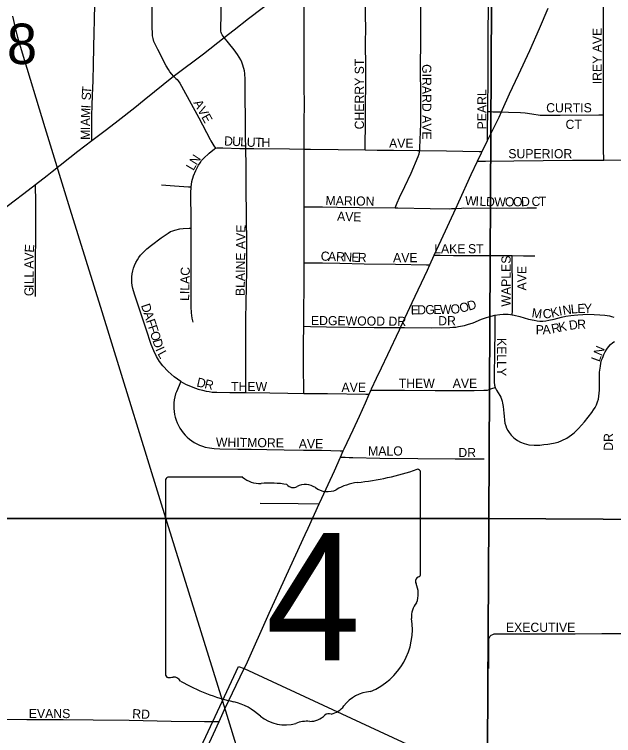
# Model space of a CAD drawing. Extents: x -97 to 34, y -21 to 22.
# Drawn here: x 5.1 to 5.72, y 18.248 to 18.994 of the extents above; entities that cross this region are included whole.
import ezdxf

# ---------------------------------------------------------------- set-up
doc = ezdxf.new("R2010")
doc.units = 0
for name, color, linetype in [('GM_X_City_Street', 7, 'Continuous'), ('GM_X_City_Street_Text', 7, 'Continuous'), ('GM_X_Corporation', 7, 'Continuous'), ('GM_X_Rail_Line', 7, 'Continuous'), ('GM_X_Section', 7, 'Continuous'), ('GM_X_Section_Text', 7, 'Continuous'), ('GM_X_State_Location', 7, 'Continuous'), ('GM_X_State_Route', 7, 'Continuous'), ('GM_X_State_Shield', 7, 'Continuous')]:
    doc.layers.add(name, color=color, linetype=linetype)

msp = doc.modelspace()

# ---------------------------------------------------------------- linework, layer by layer
at = {"layer": 'GM_X_City_Street'}
for points in [[(5.58975, 18.8933), (5.59013, 18.93041), (5.59013, 18.96145), (5.59029, 18.9801), (5.59084, 19.01111), (5.59091, 19.04212), (5.59113, 19.07316), (5.59112, 19.11343), (5.59118, 19.14442), (5.59129, 19.17858), (5.59144, 19.1837)], [(5.3172, 18.96983), (5.31523, 18.97259), (5.31429, 18.97411), (5.314, 18.975), (5.31386, 18.97623), (5.31375, 18.97746), (5.31377, 18.9795), (5.31391, 18.99294), (5.31363, 19.01437), (5.31364, 19.03294), (5.31356, 19.06369), (5.31328, 19.11002), (5.31303, 19.12908)], [(5.51942, 18.85279), (5.51963, 18.85569), (5.52056, 18.88044), (5.52045, 18.90837), (5.52015, 18.93892), (5.52047, 18.96678), (5.52058, 18.99042), (5.5204, 19.01152), (5.5206, 19.04541), (5.5203, 19.07025), (5.52029, 19.08893), (5.52037, 19.09845), (5.52047, 19.10759), (5.52043, 19.11067), (5.5202, 19.11689), (5.52, 19.11999), (5.51957, 19.12641)], [(5.46308, 18.85354), (5.46314, 18.85819), (5.4632, 18.88041), (5.46325, 18.89909), (5.46352, 18.92224), (5.46356, 18.93777), (5.46342, 18.96572), (5.46349, 18.97815), (5.46346, 18.99369), (5.46347, 19.00917), (5.46363, 19.0233), (5.46365, 19.04047), (5.46368, 19.06195), (5.46385, 19.07747), (5.46381, 19.0824)], [(5.3998, 18.85438), (5.40003, 18.88233), (5.40021, 18.90094), (5.39994, 18.91951), (5.40003, 18.94435), (5.39999, 18.96606), (5.39999, 18.97848), (5.40006, 19.00019), (5.40003, 19.00945), (5.39983, 19.01409), (5.3997, 19.01685), (5.39926, 19.01996), (5.39796, 19.0233), (5.39656, 19.02543), (5.39363, 19.02959)], [(5.18049, 18.86326), (5.18049, 18.87169), (5.18048, 18.88866), (5.18084, 18.89981), (5.18117, 18.90987), (5.1816, 18.92531), (5.18205, 18.94184), (5.18254, 18.9594), (5.18286, 18.97508), (5.18311, 18.98738), (5.18342, 19.00488), (5.18346, 19.01528)], [(5.26493, 18.92974), (5.26308, 18.93184), (5.26112, 18.93432), (5.25956, 18.93659), (5.25716, 18.94066), (5.24848, 18.95728), (5.24459, 18.96576), (5.24361, 18.96869), (5.24334, 18.97006), (5.24302, 18.97172), (5.24293, 18.97367), (5.2426, 18.98101), (5.24259, 18.99342), (5.24246, 19.01207), (5.2425, 19.01428)], [(5.70943, 18.88967), (5.70942, 18.91883), (5.70936, 18.98514), (5.70929, 19.00356), (5.70936, 19.00915)], [(5.33947, 18.8551), (5.33916, 18.86757), (5.33882, 18.92639), (5.33853, 18.9325), (5.33807, 18.93547), (5.33655, 18.94134), (5.3355, 18.94417), (5.33424, 18.9469), (5.3311, 18.95212), (5.32751, 18.9571), (5.32171, 18.96425), (5.3172, 18.96983)], [(5.26493, 18.92974), (5.26724, 18.92749), (5.26845, 18.92623), (5.26958, 18.92488), (5.27123, 18.92247), (5.27306, 18.91952), (5.291, 18.88661), (5.30255, 18.86447), (5.30344, 18.86284), (5.30663, 18.85763), (5.30832, 18.85538)], [(5.58948, 18.86336), (5.58956, 18.87486), (5.58975, 18.8933)], [(5.58975, 18.8933), (5.59203, 18.89317), (5.59504, 18.893), (5.59829, 18.89291), (5.60042, 18.89285), (5.60383, 18.89282)], [(5.60383, 18.89282), (5.61104, 18.89274), (5.62353, 18.89232), (5.62847, 18.89189), (5.63072, 18.89162), (5.63749, 18.89044), (5.64169, 18.88977), (5.64401, 18.88962), (5.66472, 18.88955), (5.70475, 18.88966), (5.70943, 18.88967)], [(5.7096, 18.84299), (5.7096, 18.8438), (5.70956, 18.85315), (5.70943, 18.88952), (5.70943, 18.88967)], [(5.28311, 18.81528), (5.28329, 18.81784), (5.28381, 18.8208), (5.28547, 18.82666), (5.28773, 18.83232), (5.29063, 18.83766), (5.29232, 18.84018), (5.29386, 18.84242), (5.29588, 18.84469), (5.30165, 18.8501), (5.30725, 18.85469), (5.30832, 18.85538)], [(5.30832, 18.85538), (5.30956, 18.85556), (5.31108, 18.85566), (5.31566, 18.8558), (5.33347, 18.85517), (5.33947, 18.8551)], [(5.33944, 18.60253), (5.33963, 18.61703), (5.33973, 18.6479), (5.33957, 18.67884), (5.34049, 18.72839), (5.34066, 18.75939), (5.34043, 18.7811), (5.33982, 18.81816), (5.33985, 18.83661), (5.33947, 18.8551)], [(5.33947, 18.8551), (5.34787, 18.855), (5.38474, 18.85459), (5.3998, 18.85438)], [(5.39994, 18.79478), (5.39986, 18.805), (5.39975, 18.84826), (5.3998, 18.85438)], [(5.3998, 18.85438), (5.40657, 18.85425), (5.4351, 18.85387), (5.46308, 18.85354)], [(5.46308, 18.85354), (5.47522, 18.85344), (5.49237, 18.85317), (5.51699, 18.85282), (5.51942, 18.85279)], [(5.49388, 18.79349), (5.49614, 18.79865), (5.49863, 18.80433), (5.50391, 18.81558), (5.51043, 18.82961), (5.51779, 18.84661), (5.5187, 18.84958), (5.51942, 18.85279)], [(5.51942, 18.85279), (5.54714, 18.85244), (5.58075, 18.85185), (5.58388, 18.8518)], [(5.57923, 18.84191), (5.58724, 18.84198), (5.61683, 18.84222), (5.67739, 18.84278), (5.7096, 18.84299)], [(5.7096, 18.84299), (5.73222, 18.84315), (5.76238, 18.84357), (5.77917, 18.84381), (5.78232, 18.84388)], [(5.12218, 18.70202), (5.12207, 18.70508), (5.12196, 18.71431), (5.12223, 18.72664), (5.12202, 18.74512), (5.12228, 18.75744), (5.12228, 18.76669), (5.12231, 18.80677), (5.12225, 18.80984), (5.12212, 18.81778)], [(5.2525, 18.81742), (5.26579, 18.81644), (5.28014, 18.81548), (5.28311, 18.81528)], [(5.28309, 18.77261), (5.28294, 18.7902), (5.28262, 18.79941), (5.28267, 18.80868), (5.28311, 18.81528)], [(5.39986, 18.73688), (5.39976, 18.74582), (5.40006, 18.77971), (5.39994, 18.79478)], [(5.39994, 18.79478), (5.40273, 18.79474), (5.41874, 18.79451), (5.43432, 18.7943), (5.45698, 18.79399), (5.49388, 18.79349)], [(5.49388, 18.79349), (5.49679, 18.79345), (5.53024, 18.7929), (5.55012, 18.79268), (5.5524, 18.79276), (5.5541, 18.79281), (5.55656, 18.79302)], [(5.55656, 18.79302), (5.56261, 18.79341), (5.56505, 18.79358), (5.59909, 18.79342), (5.63035, 18.79363), (5.64017, 18.79361)], [(5.27236, 18.61383), (5.26552, 18.61882), (5.2592, 18.62423), (5.25377, 18.63009), (5.25039, 18.63463), (5.24728, 18.63969), (5.24434, 18.64583), (5.24168, 18.65223), (5.23655, 18.66795), (5.23144, 18.68361), (5.22459, 18.70424), (5.22267, 18.71019), (5.22208, 18.71319), (5.22174, 18.71621), (5.22166, 18.71924), (5.22183, 18.7222), (5.22218, 18.72523), (5.22274, 18.72834), (5.22355, 18.73124), (5.22462, 18.7341), (5.22587, 18.73691), (5.22743, 18.73972), (5.22893, 18.74216), (5.2308, 18.74456), (5.23285, 18.74682), (5.23733, 18.75107), (5.2421, 18.75501), (5.25205, 18.7625), (5.25708, 18.76616), (5.25936, 18.76757), (5.26167, 18.76901), (5.26401, 18.76998), (5.26628, 18.77068), (5.27149, 18.77181), (5.27488, 18.77226), (5.28109, 18.77252), (5.28309, 18.77261)], [(5.28519, 18.67544), (5.28415, 18.67934), (5.28362, 18.6822), (5.28341, 18.68487), (5.28307, 18.69111), (5.28302, 18.70658), (5.28313, 18.74683), (5.28306, 18.7561), (5.28307, 18.76229), (5.28312, 18.76848), (5.28309, 18.77261)], [(5.5344, 18.74456), (5.54041, 18.74453), (5.55427, 18.74444), (5.57072, 18.74444), (5.59203, 18.74435), (5.61489, 18.74433)], [(5.61489, 18.74433), (5.62663, 18.74402), (5.63836, 18.7438)], [(5.61512, 18.68289), (5.61526, 18.68716), (5.61526, 18.69925), (5.61526, 18.70734), (5.61526, 18.71881), (5.61505, 18.73295), (5.61489, 18.74433)], [(5.39958, 18.67105), (5.39968, 18.69014), (5.39999, 18.7087), (5.39999, 18.72411), (5.39986, 18.73688)], [(5.39986, 18.73688), (5.40418, 18.73682), (5.41895, 18.73661), (5.4369, 18.73636), (5.4618, 18.73583), (5.49434, 18.7353), (5.52636, 18.73478), (5.52987, 18.73472)], [(5.49948, 18.66968), (5.50349, 18.66967), (5.53169, 18.66965), (5.5504, 18.66982), (5.55349, 18.67), (5.55656, 18.67032), (5.55962, 18.67076), (5.56567, 18.67202), (5.56865, 18.67284), (5.57452, 18.67482), (5.58325, 18.67829), (5.58857, 18.68016), (5.59319, 18.68149), (5.59719, 18.68247)], [(5.59719, 18.68247), (5.59695, 18.66615), (5.5966, 18.64427), (5.59643, 18.61947), (5.59652, 18.61324), (5.59678, 18.61025), (5.59732, 18.6079)], [(5.59719, 18.68247), (5.60234, 18.68327), (5.60564, 18.68354), (5.60804, 18.68362), (5.61079, 18.68354), (5.61311, 18.68327), (5.61512, 18.68289)], [(5.61512, 18.68289), (5.61688, 18.68261), (5.62295, 18.68113), (5.63181, 18.6786), (5.63775, 18.67727), (5.64074, 18.67681), (5.64375, 18.67654), (5.64675, 18.67646), (5.64986, 18.67675), (5.65306, 18.67728), (5.6583, 18.67853), (5.66604, 18.68049), (5.67058, 18.68147), (5.67564, 18.68227), (5.68293, 18.68307), (5.68809, 18.68343), (5.69289, 18.68352), (5.69992, 18.68334), (5.70578, 18.68298), (5.71094, 18.68263), (5.7133, 18.68231), (5.71561, 18.68187), (5.71774, 18.68125), (5.72015, 18.68044)], [(5.39948, 18.60168), (5.39944, 18.60524), (5.39922, 18.62826), (5.39909, 18.64417), (5.39919, 18.65367), (5.39958, 18.67105)], [(5.39958, 18.67105), (5.40659, 18.67094), (5.42292, 18.67064), (5.44613, 18.67028), (5.47218, 18.66977), (5.49088, 18.66971), (5.49948, 18.66968)], [(5.59732, 18.6079), (5.59875, 18.60497), (5.60052, 18.60213), (5.60221, 18.59955), (5.60319, 18.5976), (5.6039, 18.59582), (5.60453, 18.59368), (5.60506, 18.59146), (5.60569, 18.58808), (5.60613, 18.58479), (5.6064, 18.58115), (5.60667, 18.57795), (5.60702, 18.57403), (5.60756, 18.57092), (5.60827, 18.56826), (5.60925, 18.56559), (5.6105, 18.56328), (5.61201, 18.56105), (5.61405, 18.55847), (5.61636, 18.55616), (5.61823, 18.55457), (5.62054, 18.55296), (5.62366, 18.55119), (5.6273, 18.54968), (5.6297, 18.54905), (5.6321, 18.54861), (5.63762, 18.54825), (5.64357, 18.54826), (5.64767, 18.5487), (5.65193, 18.54924), (5.65762, 18.55022), (5.66242, 18.55137), (5.66634, 18.5528), (5.6714, 18.55538), (5.67647, 18.55876), (5.67903, 18.56085), (5.68344, 18.56522), (5.6897, 18.57214), (5.69368, 18.57693), (5.69743, 18.58191), (5.69916, 18.5845), (5.70076, 18.58716), (5.70218, 18.58992), (5.70334, 18.5928), (5.7042, 18.59577), (5.70475, 18.59881), (5.70504, 18.60191), (5.70515, 18.60502), (5.70515, 18.61125), (5.7053, 18.61747), (5.70544, 18.62368), (5.70615, 18.62999), (5.70668, 18.63283), (5.70749, 18.63595), (5.70862, 18.63892), (5.70977, 18.6418), (5.71116, 18.64458), (5.71278, 18.64724), (5.71464, 18.64972), (5.71679, 18.65211), (5.71902, 18.65415), (5.72063, 18.65539)], [(5.27236, 18.61383), (5.26774, 18.60328), (5.26697, 18.60103), (5.26619, 18.59807), (5.26561, 18.59507), (5.26525, 18.59205), (5.26511, 18.589), (5.26515, 18.58593), (5.26541, 18.58289), (5.26587, 18.57988), (5.26656, 18.57692), (5.26744, 18.57401), (5.26855, 18.57118), (5.2699, 18.56847), (5.27143, 18.56584), (5.27314, 18.56328), (5.27489, 18.56078), (5.27683, 18.55846), (5.27896, 18.55627), (5.28124, 18.55425), (5.28367, 18.55242), (5.28624, 18.5508), (5.28894, 18.54938), (5.29174, 18.54817), (5.2946, 18.54708), (5.29763, 18.54619), (5.30199, 18.54521), (5.3067, 18.54459), (5.31274, 18.54424), (5.33115, 18.5441), (5.3452, 18.54396), (5.36138, 18.54372), (5.37925, 18.54336), (5.39932, 18.54296), (5.41785, 18.54275), (5.43714, 18.54222), (5.44031, 18.54213)], [(5.27236, 18.61383), (5.27725, 18.61134), (5.28472, 18.60814), (5.29041, 18.6061), (5.29477, 18.60485), (5.29859, 18.60395), (5.30156, 18.60346), (5.30477, 18.60297), (5.30951, 18.60282)], [(5.46905, 18.60502), (5.4753, 18.60498), (5.5035, 18.60483), (5.53524, 18.60477), (5.55551, 18.60472), (5.57574, 18.60479), (5.58583, 18.60492), (5.58761, 18.60492), (5.58947, 18.6051), (5.59125, 18.60555), (5.59401, 18.60661), (5.59732, 18.6079)], [(5.30951, 18.60282), (5.32317, 18.60255), (5.33307, 18.60249), (5.33944, 18.60253)], [(5.33944, 18.60253), (5.36451, 18.60221), (5.38307, 18.60185), (5.39948, 18.60168)], [(5.39948, 18.60168), (5.40221, 18.60165), (5.424, 18.60142), (5.46365, 18.60098), (5.46721, 18.60095)], [(5.43748, 18.53581), (5.44239, 18.53556), (5.44634, 18.53537), (5.44831, 18.53527), (5.45018, 18.53519), (5.47819, 18.53475), (5.5174, 18.5344), (5.55608, 18.53406), (5.58595, 18.53379)], [(5.35439, 18.48811), (5.39357, 18.4876), (5.41552, 18.4875)], [(5.59318, 18.35152), (5.59497, 18.35238), (5.59633, 18.35276), (5.59763, 18.3528), (5.64888, 18.35306), (5.68008, 18.35303), (5.70783, 18.35325), (5.73129, 18.35335)], [(5.59078, 18.31697), (5.59082, 18.33324), (5.59085, 18.34701), (5.59129, 18.34858), (5.59189, 18.3501), (5.59318, 18.35152)], [(5.08138, 18.26474), (5.08526, 18.26468), (5.11323, 18.26429), (5.15055, 18.26441), (5.18164, 18.26398), (5.21896, 18.26363), (5.26248, 18.26263), (5.29669, 18.26226), (5.30795, 18.26219), (5.31192, 18.26216)]]:
    msp.add_lwpolyline(points, dxfattribs=at)
at = {"layer": 'GM_X_Corporation'}
msp.add_lwpolyline([(5.27354, 18.19364), (5.30549, 18.26216), (5.33209, 18.31915), (5.33789, 18.31695), (5.53028, 18.22764)], dxfattribs=at)
at = {"layer": 'GM_X_Rail_Line'}
msp.add_lwpolyline([(5.60523, 17.35344), (5.55562, 17.51395), (5.4983, 17.70003), (5.48173, 17.74398), (5.41338, 17.96695), (5.35777, 18.14587), (5.31905, 18.27307), (5.25811, 18.46824), (5.19106, 18.68588), (5.15793, 18.79229), (5.13207, 18.87623), (5.10765, 18.95692), (5.10388, 18.96978), (5.10128, 18.97992), (5.09855, 18.992)], dxfattribs=at)
at = {"layer": 'GM_X_Section'}
for points in [[(4.59865, 19.47855), (5.59615, 19.47364), (5.59082, 18.47236), (4.59557, 18.47233)], [(5.59615, 19.47364), (6.60805, 19.46219), (6.59547, 18.46625), (5.59082, 18.47236)], [(4.59557, 18.47233), (5.59082, 18.47236), (5.58508, 17.4654), (4.58268, 17.47301)], [(5.59082, 18.47236), (6.59547, 18.46625), (6.59419, 17.46305), (5.58508, 17.4654)]]:
    msp.add_lwpolyline(points, close=True, dxfattribs=at)
at = {"layer": 'GM_X_State_Route'}
for points in [[(5.13398, 18.82696), (5.13937, 18.83114), (5.1659, 18.85211), (5.18049, 18.86326), (5.19541, 18.87465), (5.20771, 18.88413), (5.22479, 18.89758), (5.2345, 18.90522), (5.26493, 18.92974), (5.26591, 18.93054), (5.29566, 18.95309), (5.3172, 18.96983), (5.32755, 18.97789), (5.34224, 18.98932), (5.36921, 19.01034)], [(5.40398, 18.46209), (5.41552, 18.4875), (5.41818, 18.49342), (5.43113, 18.52166), (5.43748, 18.53581), (5.44031, 18.54213), (5.4413, 18.54434), (5.45051, 18.56398), (5.45702, 18.5781), (5.46318, 18.59192), (5.46721, 18.60095), (5.46823, 18.60321), (5.46905, 18.60502), (5.46962, 18.60627), (5.47483, 18.61741), (5.47992, 18.62801), (5.48652, 18.64198), (5.49839, 18.66735), (5.49948, 18.66968), (5.51155, 18.69552), (5.52737, 18.7293), (5.52987, 18.73472), (5.5344, 18.74456), (5.54166, 18.76034), (5.55656, 18.79302), (5.55969, 18.79996), (5.57274, 18.82809), (5.57923, 18.84191), (5.5833, 18.8506), (5.58388, 18.8518), (5.58948, 18.86336), (5.59276, 18.87012), (5.60148, 18.88745), (5.60383, 18.89282), (5.60497, 18.89534), (5.6122, 18.91142), (5.6215, 18.93108), (5.63325, 18.95654), (5.64341, 18.97929), (5.6523, 19.00021)], [(4.98638, 18.71231), (5.03452, 18.75017), (5.05126, 18.76358), (5.08681, 18.79085), (5.09993, 18.80091), (5.1099, 18.80832), (5.12212, 18.81778), (5.13398, 18.82696)], [(5.33789, 18.31695), (5.33975, 18.32101), (5.36385, 18.37438), (5.38178, 18.41362), (5.40105, 18.45562), (5.40398, 18.46209)], [(5.24782, 18.12447), (5.25533, 18.13978), (5.26828, 18.16788), (5.28022, 18.19353), (5.29829, 18.23237), (5.31192, 18.26216), (5.31759, 18.27456), (5.33789, 18.31695)]]:
    msp.add_lwpolyline(points, dxfattribs=at)
at = {"layer": 'GM_X_State_Shield'}
for p, q in [((5.52016, 18.41509), (5.52016, 18.51978)), ((5.25649, 18.51137), (5.25649, 18.31125)), ((5.3363, 18.51482), (5.25909, 18.51482)), ((5.52013, 18.41512), (5.52016, 18.41509))]:
    msp.add_line(p, q, dxfattribs=at)
for centre, radius, start, end in [((5.42623, 18.78765), 0.27962, 275.84447, 288.90645), ((5.51723, 18.52021), 0.00294, 351.86209, 97.738), ((5.25951, 18.5118), 0.00305, 98.1301, 188.1301), ((5.35469, 18.53805), 0.02963, 231.61951, 271.11188), ((5.4619, 18.4537), 0.05625, 97.34618, 120.76885), ((5.36451, 18.40247), 0.10636, 80.48669, 94.98827), ((5.38866, 18.51284), 0.00855, 219.79206, 297.10237), ((5.40121, 18.48971), 0.01777, 54.46668, 119.14113), ((5.42415, 18.52143), 0.02138, 233.85621, 294.82819), ((5.51703, 18.41469), 0.00314, 289.60381, 7.73413), ((5.51948, 18.40741), 0.00454, 107.94398, 210.33697), ((5.49058, 18.39417), 0.02727, 340.03296, 23.64957), ((5.53067, 18.37128), 0.01984, 136.8065, 186.92959), ((5.4419, 18.35796), 0.06994, 292.30889, 8.98584), ((5.25954, 18.31082), 0.00308, 171.95839, 258.30661), ((5.26001, 18.33129), 0.02352, 267.33899, 280.60386), ((5.26482, 18.29971), 0.00848, 29.74838, 93.27175), ((5.37188, 18.47951), 0.20192, 240.41292, 257.1985), ((5.47139, 18.25507), 0.0383, 94.40312, 142.57675), ((5.31168, 18.22135), 0.06318, 47.18416, 75.83597), ((5.42286, 18.29186), 0.0226, 282.87319, 323.27711), ((5.38001, 18.29872), 0.04009, 230.70037, 286.29184), ((5.4061, 18.28373), 0.02136, 268.77702, 315.54927), ((5.42542, 18.26435), 0.00601, 65.75173, 132.64842), ((5.40317, 18.22953), 0.03294, 85.69512, 111.20995)]:
    msp.add_arc(centre, radius, start, end, dxfattribs=at)

# ---------------------------------------------------------------- texts
at = {"layer": 'GM_X_City_Street_Text'}
for s, height, rotation, p in [('IREY AVE', 0.00947, 90, (5.70754, 18.92145)), ('CHERRY ST', 0.00947, 90, (5.46171, 18.87478)), ('GIRARD AVE', 0.00947, 270, (5.52194, 18.94228)), ('S', 0.00947, 88.27836, (5.17921, 18.9047)), ('T', 0.00947, 85.34981, (5.1794, 18.91124)), ('PEARL', 0.00947, 90, (5.58838, 18.87478)), ('I', 0.00947, 86.23825, (5.17887, 18.89627)), ('AVE', 0.00947, 299.25096, (5.28505, 18.90232)), ('CURTIS', 0.00947, 0.00001, (5.65016, 18.8924)), ('M', 0.00947, 87.35773, (5.17841, 18.88633)), ('A', 0.00947, 89.84697, (5.17839, 18.87811)), ('CT', 0.00947, 0.00001, (5.67016, 18.87527)), ('I', 0.00947, 89.95628, (5.17839, 18.87395)), ('M', 0.00947, 89.96357, (5.17838, 18.86395)), ('D', 0.00947, 356.93897, (5.31692, 18.85822)), ('U', 0.00947, 356.91715, (5.32525, 18.85778)), ('L', 0.00947, 356.9496, (5.33358, 18.85733)), ('U', 0.00947, 357.61313, (5.34035, 18.85697)), ('T', 0.00947, 359.56248, (5.34902, 18.85661)), ('H', 0.00947, 359.99149, (5.35576, 18.85656)), ('AVE', 0.00947, 0.00001, (5.48766, 18.85573)), ('SUPERIOR', 0.00947, 0.00001, (5.61099, 18.8449)), ('N', 0.00947, 57.35276, (5.2886, 18.83713)), ('L', 0.00947, 59.48597, (5.28526, 18.83147)), ('MARION', 0.00947, 358.97529, (5.42188, 18.79656)), ('W', 0.00947, 357.17453, (5.56608, 18.79656)), ('I', 0.00947, 357.15724, (5.5769, 18.79602)), ('L', 0.00947, 357.15085, (5.58106, 18.79582)), ('D', 0.00947, 357.18919, (5.58773, 18.79549)), ('W', 0.00947, 359.7945, (5.59652, 18.79507)), ('O', 0.00947, 0.90537, (5.60755, 18.79503)), ('O', 0.00947, 0.92786, (5.61589, 18.79516)), ('D', 0.00947, 0.93858, (5.62422, 18.7953)), ('C', 0.00947, 0.92287, (5.63507, 18.79547)), ('T', 0.00947, 0.93643, (5.64257, 18.79559)), ('A', 0.00947, 357.87971, (5.43379, 18.78028)), ('V', 0.00947, 357.9211, (5.44213, 18.77997)), ('E', 0.00947, 358.29811, (5.45052, 18.77967)), ('BLAINE AVE', 0.00947, 89.30946, (5.33838, 18.70231)), ('LAKE', 0.00947, 0.00001, (5.53433, 18.74656)), ('ST', 0.00947, 0.00001, (5.56933, 18.74656)), ('E', 0.00947, 85.98055, (5.12027, 18.7471)), ('C', 0.00947, 357.91126, (5.4169, 18.73906)), ('V', 0.00947, 88.57936, (5.12007, 18.73888)), ('A', 0.00947, 357.90155, (5.42439, 18.73879)), ('R', 0.00947, 357.91472, (5.43272, 18.73848)), ('N', 0.00947, 357.9211, (5.44022, 18.73821)), ('E', 0.00947, 357.89609, (5.44854, 18.73791)), ('R', 0.00947, 358.24792, (5.45527, 18.73766)), ('AVE', 0.00947, 0.00001, (5.49183, 18.7374)), ('WAPLES', 0.00947, 90, (5.61338, 18.69145)), ('A', 0.00947, 89.95627, (5.12006, 18.73061)), ('L', 0.00947, 89.97066, (5.12006, 18.72145)), ('LILAC', 0.00947, 88.63187, (5.28088, 18.69722)), ('AVE', 0.00947, 90, (5.62967, 18.70811)), ('L', 0.00947, 89.97066, (5.12005, 18.71478)), ('G', 0.00947, 89.97813, (5.12005, 18.70228)), ('I', 0.00947, 89.95628, (5.12005, 18.71061)), ('D', 0.00947, 16.56864, (5.57016, 18.68717)), ('D', 0.00947, 288.02028, (5.23105, 18.69274)), ('E', 0.00947, 0.98352, (5.5102, 18.68323)), ('D', 0.00947, 0.98362, (5.51687, 18.68335)), ('G', 0.00947, 0.98362, (5.5252, 18.68349)), ('E', 0.00947, 1.01138, (5.53354, 18.68363)), ('W', 0.00947, 0.9753, (5.5402, 18.68375)), ('O', 0.00947, 4.46346, (5.55166, 18.68396)), ('O', 0.00947, 15.04495, (5.56185, 18.68493)), ('M', 0.00947, 352.23566, (5.63475, 18.68044)), ('C', 0.00947, 5.38814, (5.64703, 18.67904)), ('K', 0.00947, 13.78316, (5.65598, 18.68)), ('I', 0.00947, 10.82112, (5.66395, 18.68196)), ('N', 0.00947, 9.28625, (5.66797, 18.68273)), ('L', 0.00947, 6.132, (5.67606, 18.68406)), ('E', 0.00947, 1.03815, (5.68246, 18.68475)), ('Y', 0.00947, 0.13116, (5.68909, 18.68487)), ('A', 0.00947, 288.02106, (5.23363, 18.68481)), ('EDGEWOOD DR', 0.0094697, 359.44379, (5.40684, 18.67239)), ('DR', 0.00947, 0.00001, (5.53849, 18.67211)), ('F', 0.00947, 288.02073, (5.23621, 18.67689)), ('R', 0.00947, 13.01676, (5.65662, 18.66355)), ('K', 0.00947, 11.41707, (5.66386, 18.66523)), ('D', 0.00947, 7.60764, (5.67433, 18.66728)), ('R', 0.00947, 1.77322, (5.68233, 18.66836)), ('F', 0.00947, 288.02073, (5.23827, 18.67055)), ('P', 0.00947, 0.10929, (5.63933, 18.66277)), ('A', 0.00947, 3.47872, (5.64661, 18.6628)), ('O', 0.00947, 288.02106, (5.24033, 18.66421)), ('D', 0.00947, 288.03547, (5.24291, 18.65629)), ('KELLY', 0.00947, 270, (5.59941, 18.65895)), ('I', 0.00947, 294.23788, (5.2459, 18.64732)), ('L', 0.00947, 298.67549, (5.24796, 18.6428)), ('N', 0.00947, 66.98506, (5.70746, 18.63981)), ('L', 0.00947, 69.54307, (5.70517, 18.63367)), ('D', 0.00947, 347.10369, (5.28809, 18.60901)), ('R', 0.00947, 347.08789, (5.29621, 18.60715)), ('THEW', 0.00947, 0.00001, (5.49766, 18.60739)), ('AVE', 0.00947, 0.00001, (5.55349, 18.60739)), ('THEW', 0.00947, 0.00001, (5.32433, 18.60406)), ('AVE', 0.00947, 0.00001, (5.43849, 18.60323)), ('WHITMORE', 0.00947, 359.2713, (5.30856, 18.54656)), ('AVE', 0.00947, 0.00001, (5.39433, 18.54489)), ('DR', 0.00947, 90, (5.71921, 18.54228)), ('MALO', 0.00947, 0.00001, (5.46599, 18.53739)), ('DR', 0.00947, 0.00001, (5.55933, 18.53573)), ('EXECUTIVE', 0.00947, 0.00001, (5.60849, 18.3549)), ('EVANS', 0.00947, 0.00001, (5.11516, 18.26573)), ('RD', 0.00947, 356.98902, (5.22192, 18.26572))]:
    msp.add_text(s, height=height, rotation=rotation, dxfattribs=at).set_placement(p)
at = {"layer": 'GM_X_Section_Text'}
msp.add_text('28', height=0.041856, rotation=0.00001, dxfattribs=at).set_placement((5.06141, 18.94234))
at = {"layer": 'GM_X_State_Location'}
for s in ['s', 'r']:
    msp.add_text(s, height=0.000189, dxfattribs=at).set_placement((5.38535, 18.39801))
msp.add_text('4', height=0.000189, rotation=0.00001, dxfattribs=at).set_placement((5.35683, 18.38423))
at = {"layer": 'GM_X_State_Shield'}
msp.add_text('4', height=0.13184, dxfattribs=at).set_placement((5.36029, 18.32537))

doc.saveas('drawing.dxf')
